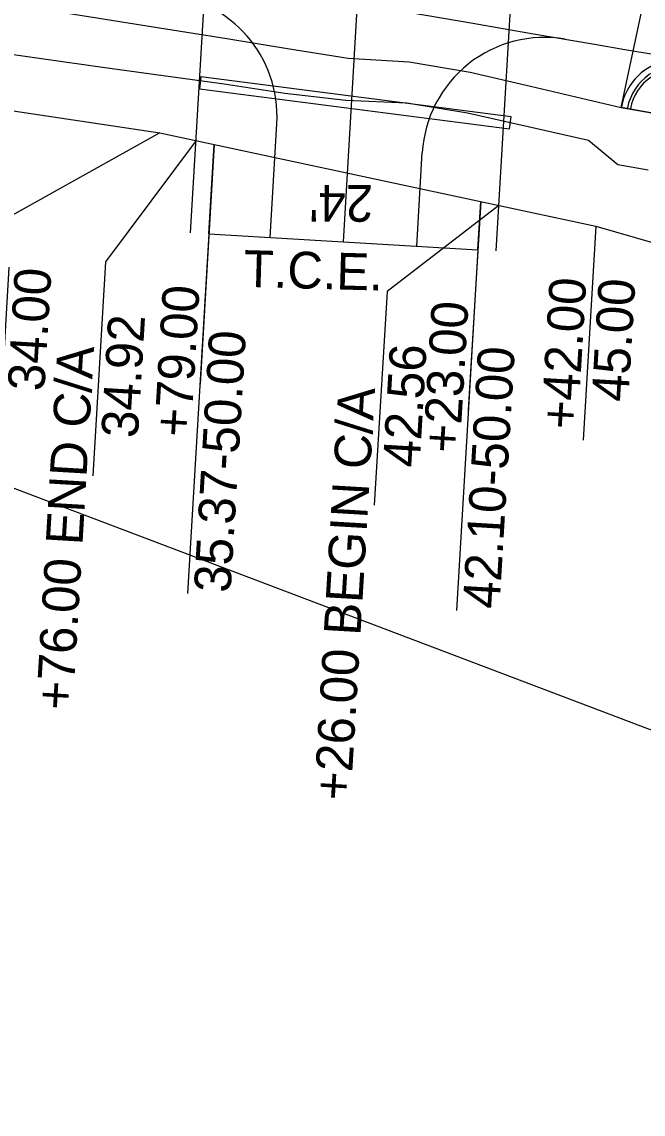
# Model space of a CAD drawing. Extents: x -70 to 701944, y -4 to 666871.
# Drawn here: x 663904.6 to 664006.1, y 656567.8 to 656746.2 of the extents above; entities that cross this region are included whole.
import ezdxf

# ---------------------------------------------------------------- set-up
doc = ezdxf.new("R2010")
doc.units = 0
for name, color, linetype in [('R_Detour', 7, 'Continuous'), ('R_Drive', 7, 'Continuous'), ('R_No Plot', 7, 'Continuous'), ('R_Proposed Const Limits', 7, 'Continuous'), ('R_Proposed Road', 7, 'Continuous'), ('R_ROW', 7, 'Continuous'), ('R_ROW Annot', 7, 'Continuous'), ('R_Temp Easement', 7, 'Continuous'), ('R_Temp Easement Annot', 7, 'Continuous'), ('R_Water', 7, 'Continuous')]:
    doc.layers.add(name, color=color, linetype=linetype)

msp = doc.modelspace()

# ---------------------------------------------------------------- linework, layer by layer
at = {"layer": 'R_Detour'}
msp.add_lwpolyline([(663872.16, 656681.83), (664839.63, 656314.9), (664749.31, 656473.74)], dxfattribs=at)
at = {"layer": 'R_Drive'}
for p, q in [((663945.2, 656710.97), (663946.3, 656729.55)), ((663969.15, 656709.54), (663970.06, 656724.84))]:
    msp.add_line(p, q, dxfattribs=at)
for centre, start, end in [((663926.34, 656730.74), 356.5915, 85.4459), ((663990.03, 656723.65), 80.2515, 176.5915)]:
    msp.add_arc(centre, 20, start, end, dxfattribs=at)
at = {"layer": 'R_No Plot'}
for p, q in [((663932.22, 656711.74), (663935.19, 656761.65)), ((663957.17, 656710.25), (663960.15, 656760.17)), ((663982.13, 656708.77), (663985.1, 656758.68))]:
    msp.add_line(p, q, dxfattribs=at)
msp.add_lwpolyline([(664002.56, 656732.2), (664007.87, 656757.32), (664066.52, 656753.83), (664146.1, 656731.41), (664131.42, 656679.33), (664092.48, 656701.38), (664066.38, 656716.16), (664043.95, 656724.74)], close=True, dxfattribs=at)
at = {"layer": 'R_Proposed Const Limits'}
for points in [[(663878.11, 656745.22), (663888.03, 656743.46), (663897.93, 656741.63), (663907.87, 656740.2), (663917.8, 656738.8), (663927.74, 656737.45), (663937.67, 656736.07)], [(663937.67, 656736.07), (663947.6, 656734.56), (663957.55, 656733.41), (663967.54, 656732.95)], [(663967.54, 656732.95), (663977.46, 656731.31), (663987.35, 656729.08), (663997.23, 656726.88), (664002, 656722.88), (664006.96, 656722.03)]]:
    msp.add_lwpolyline(points, dxfattribs=at)
at = {"layer": 'R_Proposed Road'}
for points in [[(663858.73, 656756.19), (663868.7, 656755.39), (663878.67, 656754.6), (663888.64, 656753.81), (663898.61, 656753.01), (663908.58, 656752.22), (663918.55, 656751.42), (663928.52, 656750.63), (663938.49, 656749.84), (663948.46, 656749.04), (663958.44, 656748.25), (663968.42, 656747.65), (663978.33, 656745.95), (663988.25, 656744.24), (663998.17, 656742.54), (664003.12, 656741.69)], [(663858.73, 656756.19), (663868.65, 656754.6), (663878.58, 656753), (663888.5, 656751.41), (663898.42, 656749.82), (663908.35, 656748.22), (663918.27, 656746.63), (663928.19, 656745.04), (663938.11, 656743.45), (663948.04, 656741.85), (663957.96, 656740.26), (663967.94, 656739.67), (663977.86, 656737.96), (663987.74, 656735.66), (664002.56, 656732.2)], [(664003.12, 656741.69), (664008.08, 656740.84)], [(664002.56, 656732.2), (664007.52, 656731.34), (664008.56, 656731.16), (664017.43, 656729.64), (664027.35, 656727.94), (664031.55, 656727.21), (664033.92, 656726.81), (664036.92, 656726.24), (664036.96, 656726.23), (664040, 656725.61), (664043.02, 656724.96), (664044.88, 656724.53)]]:
    msp.add_lwpolyline(points, dxfattribs=at)
for radius in [9.5, 8.5, 8]:
    msp.add_arc((664011.92, 656730.54), radius, 79.1723, 169.1723, dxfattribs=at)
at = {"layer": 'R_ROW'}
msp.add_lwpolyline([(663857.84, 656741.21), (663882.5, 656734.74), (663927.18, 656728.07), (663998.4, 656712.81), (664049.42, 656698.11), (664139.72, 656649.43), (664236.9, 656635.99), (664280.86, 656611.19), (664357.07, 656584.26)], dxfattribs=at)
at = {"layer": 'R_ROW Annot'}
for points in [[(663927.18, 656728.07), (663903.01, 656714.55), (663900.93, 656679.61)], [(663933.12, 656726.8), (663918.3, 656706.96), (663916.22, 656672.02)], [(663982.57, 656716.2), (663964.31, 656702.15), (663962.22, 656667.21)], [(663998.4, 656712.81), (663996.32, 656677.87)]]:
    msp.add_lwpolyline(points, dxfattribs=at)
at = {"layer": 'R_Temp Easement'}
for p, q in [((663935.21, 656711.56), (663936.08, 656726.16)), ((663979.14, 656708.95), (663979.61, 656716.84)), ((663935.21, 656711.56), (663979.14, 656708.95))]:
    msp.add_line(p, q, dxfattribs=at)
at = {"layer": 'R_Temp Easement Annot'}
for points in [[(663936.08, 656726.16), (663933.75, 656687)], [(663979.61, 656716.84), (663977.58, 656682.78)], [(663935.21, 656711.56), (663931.71, 656652.79)], [(663979.14, 656708.95), (663975.63, 656650.02)]]:
    msp.add_lwpolyline(points, dxfattribs=at)
at = {"layer": 'R_Water'}
msp.add_lwpolyline([(663933.91, 656737.22), (663933.66, 656735.23), (663984.32, 656728.71), (663984.57, 656730.69)], close=True, dxfattribs=at)

# ---------------------------------------------------------------- texts
at = {"layer": 'R_Drive'}
msp.add_text("24'", height=6, rotation=179.7886, dxfattribs=at).set_placement((663962.05, 656719.53))
at = {"layer": 'R_ROW Annot'}
for s, p in [('34.00', (663908.31, 656685.77)), ('+42.00', (663995.41, 656679.52)), ('45.00', (664003.7, 656684.03)), ('34.92', (663923.59, 656678.12)), ('+76.00 END C/A', (663912.93, 656633.67)), ('42.56', (663969.6, 656673.31)), ('+26.00 BEGIN C/A', (663958.34, 656618.89))]:
    msp.add_text(s, height=6, rotation=86.5917, dxfattribs=at).set_placement(p)
at = {"layer": 'R_Temp Easement Annot'}
for s, rotation, p in [('T.C.E.', 358.4064, (663940.82, 656702.91)), ('+79.00', 86.5917, (663932.23, 656678.27)), ('+23.00', 86.5917, (663976.15, 656675.66)), ('35.37-50.00', 86.5917, (663938.73, 656652.84)), ('42.10-50.00', 86.5917, (663982.65, 656650.22))]:
    msp.add_text(s, height=6, rotation=rotation, dxfattribs=at).set_placement(p)

doc.saveas('drawing.dxf')
